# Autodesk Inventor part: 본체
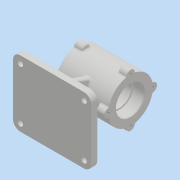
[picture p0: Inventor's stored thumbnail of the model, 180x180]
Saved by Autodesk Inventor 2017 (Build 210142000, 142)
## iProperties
Part Number: 본체
Material: 일반
Document SubType Name: Modeling
Designer: MRC
Density: 1 g/cm^3
Appearance: 기본값
Author: MRC
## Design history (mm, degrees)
sketch "스케치1"
  geometry: L1 (-70.407, 0)-(70.407, 0); L2 (-43.5, 23.5)-(-43.5, 37); L3 (-43.5, 37)-(43.5, 37); L4 (43.5, 37)-(43.5, 23.5); L5 (-43.5, 23.5)-(-24.5, 23.5); L6 (-24.5, 23.5)-(-24.5, 21); L7 (-24.5, 21)-(24.5, 21); L8 (24.5, 21)-(24.5, 23.5); L9 (24.5, 23.5)-(43.5, 23.5); 3 further points
  constraints: 18 end point, 6 perpendicular, 2 midpoint, 2 point on line, 1 coincident, 1 collinear, 1 horizontal, 1 vertical, 1 vertical alignment
  dimensions: "d0" = 74 diameter of L3 L1; "d1" = 87 distance of L2.end L3.end; "d2" = 47 diameter of L5 L1; "d3" = 42 diameter of L7 L1; "d4" = 19 distance of L2.start L5.end
revolve "회전1" sketch "스케치1" stored, may be unused: angle "d5" = 90 deg
sketch "스케치2"
  geometry: C1 r 7 at (0, 37); 2 further points
  constraints: 2 vertical alignment, 1 centre point, 1 other
  dimensions: "d6" = 14 diameter of C1
extrude "돌출1" join sketch "스케치2" distance "d7" = 14; taper "d8" = 0 deg
fillet "모깎기1" dims "d9" = 3
sketch "스케치3"
  geometry: 3 further points
  constraints: 1 vertical alignment, 1 other
hole "구멍1" sketch "스케치3" at (0, 0) diameter "d10" = 3.242; stored, may be unused: countersink angle "d14" = 90 deg, drill point angle "d16" = 118 deg; dims "d11" = 8, "d12" = 4, "d13" = 2, "d15" = 10
chamfer "모따기1" distance "d20" = 1; stored, may be unused: second distance "d21" = 2, angle "d22" = 45 deg
node "작업 평면1"
sketch "스케치4"
  geometry: L1 (-48, -55)-(58, -55); L2 (70, -43)-(70, 43); L3 (58, 55)-(-48, 55); L4 (-60, 43)-(-60, -43); C1 r 4.5 at (58, -43); C2 r 4.5 at (58, 43); C3 r 4.5 at (-48, 43); C4 r 4.5 at (-48, -43); A1 r 12 centre (58, -43) between (58, -55) and (70, -43); A2 r 12 centre (58, 43) between (70, 43) and (58, 55); A3 r 12 centre (-48, 43) between (-48, 55) and (-60, 43); A4 r 12 centre (-48, -43) between (-60, -43) and (-48, -55); 5 further points
  constraints: 8 centre point, 8 end point, 8 point on circle, 8 tangent, 6 point on line, 4 coincident, 3 equal radius, 2 parallel, 1 horizontal, 1 horizontal alignment, 1 midpoint, 1 perpendicular
  dimensions: "d24" = 130 distance of point (-60, -55) point (70, -55); "d25" = 110 distance of point (-60, 55) point (-60, -55); "d26" = 70 distance from line of L2 point (0, 0); "d27" = 12 radius of A1; "d28" = 9 diameter of C1; "d29" = 9 diameter of C2; "d30" = 9 diameter of C3; "d31" = 9 diameter of C4
extrude "돌출2" join sketch "스케치4" distance "d32" = 12; taper "d33" = 0 deg
sketch "스케치5"
  geometry: L1 (5, -5)-(-5, -5); L2 (-5, -5)-(-5, 5); L3 (-5, 5)-(5, 5); L4 (5, 5)-(5, -5); 3 further points
  constraints: 8 end point, 2 midpoint, 2 parallel, 1 horizontal, 1 horizontal alignment, 1 perpendicular, 1 vertical alignment
  dimensions: "d34" = 10 distance of L3.end L1.start; "d35" = 10 distance of L1.start L1.end
extrude "돌출3" join sketch "스케치5" stored distance "d36" = 10; taper "d37" = 0 deg
sketch "스케치6"
  geometry: L1 (16.172, -32.008)-(30, -70); L2 (-58, -70)-(48, -70) reference; 1 further point
  constraints: 2 end point, 1 point on line
  dimensions: "d38" = 110 deg angle of L2 L1; "d39" = 30 horizontal distance of point (0, 0) L1.end
feature "리브1" sketch "스케치6" dims "d40" = 1, "d41" = 10, "d42" = 0, "d43" = 0, "d44" = 1, "d45" = 1
sketch "스케치7"
  geometry: L1 (-70, -43)-(-70, 43) reference; L2 (-70, 41)-(-23.638, 24.126); L3 (-82, 55)-(-70, 55) reference; 1 further point
  constraints: 2 end point, 1 point on line
  dimensions: "d46" = 110 deg angle of L1 L2; "d47" = 14 distance from line of L3 L2.start
feature "리브2" sketch "스케치7" dims "d48" = 1, "d49" = 10, "d50" = 0, "d51" = 0, "d52" = 1, "d53" = 1
fillet "모깎기2" dims "d54" = 3
fillet "모깎기3" dims "d58" = 1
sketch "스케치9"
  geometry: L1 (-59.202, 20.739)-(-59.202, -20.739); L2 (-59.202, -20.739)-(-56.798, -20.739); L3 (-56.798, -20.739)-(-56.798, 20.739); L4 (-56.798, 20.739)-(-59.202, 20.739); 4 further points
  constraints: 2 horizontal alignment, 1 vertical alignment, 2 other
  dimensions: "d59" = 58 distance of point (0, 0) point (-58, 0)
feature "엠보싱2" sketch "스케치9" dims "d60" = 0.5, "d61" = 0
node "솔리드1"
pattern_circular "원형 패턴1" dims angle "d18" = 360 deg
mirror "미러1"
mirror "미러2"
mirror "미러3"
other parameters: "d23" = -82
